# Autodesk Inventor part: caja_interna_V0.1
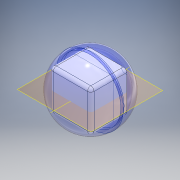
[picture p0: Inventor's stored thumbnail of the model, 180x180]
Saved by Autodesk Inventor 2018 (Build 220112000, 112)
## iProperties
Created: 2018-09
Part Number: caja_interna_V0.1
Material: Generic
Document SubType Name: Modeling
Designer: Gordillo
Density: 1 g/cm^3
Appearance: Default
Author: Gordillo
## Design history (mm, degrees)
sketch "Sketch1"
  geometry: L1 (125, 125)-(-125, 125); L2 (-125, 125)-(-125, -125); L3 (-125, -125)-(125, -125); L4 (125, -125)-(125, 125); L5 (-175, 0)-(175, 0) reference; L6 (0, -175)-(0, 175) reference; 1 further point
  constraints: 8 end point, 2 parallel, 1 horizontal, 1 perpendicular, 2 other
  dimensions: "d0" = 250 distance of L3.end L2.end; "d1" = 250 distance of L2.end L1.end
extrude "Extrusion1" new body sketch "Sketch1" distance "d2" = 220; taper "d3" = 0 deg
fillet "Fillet1" dims "d5" = 20
sketch "Sketch2"
  geometry: L1 (20, 125)-(220, 125) reference; L2 (120, 125)-(120, -125); L3 (220, -125)-(20, -125) reference; L4 (120, 125)-(120, 205); L5 (120, 0)-(-80, 0); L6 (-153.152, 0)-(282.192, 0) reference; A1 r 203.001 centre (122.991, 2.021) between (120, 205) and (-80, 0); 1 further point
  constraints: 6 end point, 3 midpoint, 2 point on circle, 1 centre point, 1 horizontal, 1 vertical
  dimensions: "d6" = 200 distance of L5.start L5.end; "d8" = 80 distance of L2.start L4.end
revolve "Revolution1" sketch "Sketch2" stored, may be unused: angle "d9" = 90 deg
combine "Combine1"
shell "Shell2" dims "d10" = 25
sketch "Sketch3"
  geometry: L1 (100, 100)-(100, -100) reference; L2 (100, -100)-(-100, -100) reference; L3 (-100, -100)-(-100, 100) reference; L4 (-100, 100)-(100, 100) reference; L5 (105, 125)-(-105, 125) reference; L6 (-125, 105)-(-125, -105) reference; L7 (-105, -125)-(105, -125) reference; L8 (125, -105)-(125, 105) reference; L9 (-105, 125)-(105, 125) reference; L10 (125, 105)-(125, -105) reference; L11 (105, -125)-(-105, -125) reference; L12 (-125, -105)-(-125, 105) reference; L13 (-105, 125)-(105, 125) reference; L14 (105, 125)-(-105, 125); L15 (-105, 125)-(-125, 105); L16 (-125, -105)-(-125, 105) reference; L17 (-125, -105)-(-105, -125); L18 (125, 105)-(125, -105) reference; L19 (105, -125)-(125, -105); L20 (125, -105)-(125, 105); L21 (-125, 105)-(-105, 105) reference; L22 (-125, 105)-(-125, -105); L23 (-105, -125)-(105, -125); C1 r 205 at (0, 0) reference; C2 r 189 at (0, 0); C3 r 205 at (0, 0) reference; A1 r 20 centre (105, 105) between (125, 105) and (105, 125) reference; A2 r 20 centre (-105, 105) between (-105, 125) and (-125, 105) reference; A3 r 20 centre (-105, -105) between (-125, -105) and (-105, -125) reference; A4 r 20 centre (105, -105) between (105, -125) and (125, -105) reference; A5 r 20 centre (-105, 105) between (-105, 125) and (-125, 105) reference; A6 r 20 centre (105, 105) between (125, 105) and (105, 125) reference; A7 r 20 centre (105, -105) between (105, -125) and (125, -105) reference; A8 r 20 centre (-105, -105) between (-125, -105) and (-105, -125) reference; A9 r 20 centre (105, 105) between (125, 105) and (105, 125) reference; A10 r 20 centre (105, 105) between (125, 105) and (105, 125); A11 r 20 centre (105, -105) between (105, -125) and (125, -105) reference; A12 r 20 centre (105, -105) between (105, -125) and (125, -105); A13 r 20 centre (-105, -105) between (-125, -105) and (-105, -125); A14 r 20 centre (-105, 105) between (-105, 125) and (-125, 105) reference; A15 r 20 centre (-105, 105) between (-105, 125) and (-125, 105); A16 r 20 centre (-105, -105) between (-125, -105) and (-105, -125); A17 r 20 centre (-105, -105) between (-125, -105) and (-105, -125); A18 r 20 centre (105, -105) between (105, -125) and (125, -105); A19 r 20 centre (-105, -105) between (-125, -105) and (-105, -125) reference; A20 r 20 centre (-105, -105) between (-125, -105) and (-105, -125); 1 further point
  constraints: 16 point on circle, 14 end point, 9 centre point, 3 perpendicular, 3 tangent, 2 collinear, 1 concentric, 1 vertical
  dimensions: "d11" = 16 radial gap between concentric circles of C1 C2
extrude "Extrusion2" join sketch "Sketch3" distance "d12" = 20; taper "d13" = 0 deg
sketch "Sketch4"
  geometry: L1 (189, 140)-(-189, 140) reference; L2 (205, 120)-(-205, 120) reference; L3 (189, 120)-(189, 140) reference; L4 (189, 140)-(-189, 140) reference; L5 (-189, 120)-(189, 120) reference; L6 (-125, 20)-(-125, 220) reference; L7 (-125, 220)-(-105, 220) reference; L8 (-205, 120)-(-189, 120); L9 (-189, 120)-(-189, 140); L10 (205, 120)-(-205, 120) reference; L11 (-189, 140)-(-125, 140); L12 (0, 120)-(0, 320); L13 (-125, 140)-(0, 140); L14 (0, -168.98)-(0, 453.807) reference; A1 r 195 centre (-10.071, 125.26) between (0, 320) and (-205, 120); A2 r 189.427 centre (-1.871, 110.582) between (0, 300) and (-189, 140); 2 further points
  constraints: 10 end point, 4 point on circle, 4 point on line, 2 centre point, 2 midpoint, 1 collinear, 1 perpendicular, 1 vertical
  dimensions: "d14" = 200 distance of L12.start L12.end; "d15" = 195 radius of A1; "d16" = 20 distance of L12.end A2.start
revolve "Revolution2" sketch "Sketch4" stored, may be unused: angle "d17" = 90 deg
combine "Combine2"
node "cajacorchopan"
node "semicirculo_inferior"
node "Projected Loop1"
node "Projected Loop2"
node "Projected Loop3"
node "Projected Loop4"
node "semicirculo_superior"
